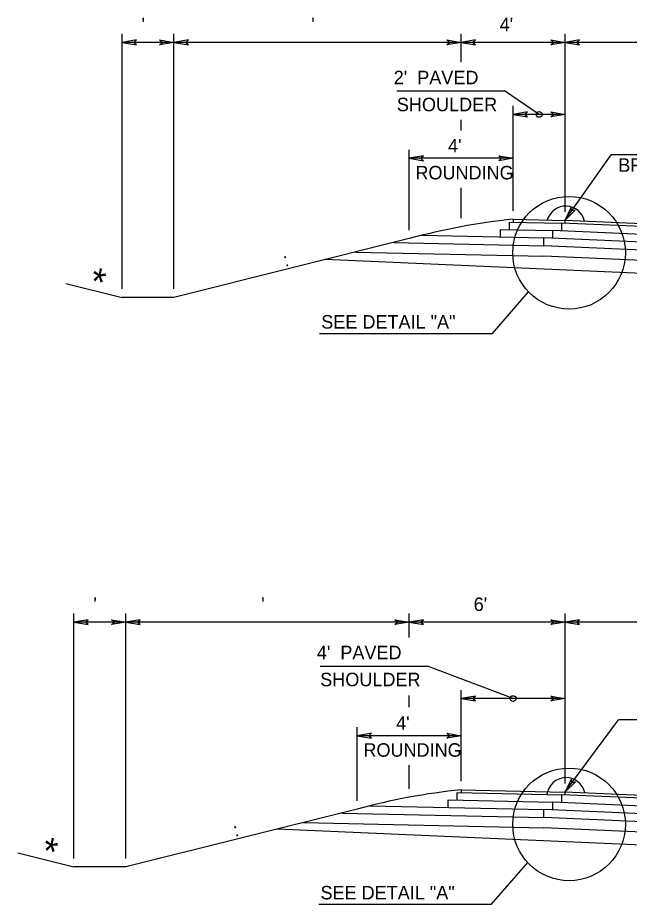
# Model space of a CAD drawing. Extents: x -592 to 1199, y -590 to 416.
# Drawn here: x 726.1 to 789.6, y -200.2 to -108.4 of the extents above; entities that cross this region are included whole.
import ezdxf

# ---------------------------------------------------------------- set-up
doc = ezdxf.new("R2010")
doc.units = 0
doc.layers.add('1', color=7, linetype='Continuous')
doc.layers.add('Des_ Drain_ Ftrs', color=7, linetype='Continuous')

msp = doc.modelspace()

# ---------------------------------------------------------------- linework, layer by layer
at = {"layer": '1'}
for p, q in [((736.954, -136.465), (736.954, -110.022)), ((742.343, -136.465), (742.343, -110.022)), ((772.114, -112.972), (772.114, -110.022)), ((782.89, -128.477), (782.89, -110.022)), ((742.343, -110.902), (736.954, -110.902)), ((772.114, -110.902), (742.343, -110.902)), ((782.89, -110.902), (772.114, -110.902)), ((812.526, -110.902), (782.89, -110.902)), ((765.454, -115.944), (776.595, -115.944)), ((780.196, -118.369), (776.61, -115.923)), ((777.502, -128.359), (777.502, -117.489)), ((782.89, -118.369), (777.502, -118.369)), ((772.114, -120.033), (772.114, -118.951)), ((766.726, -130.369), (766.726, -122.044)), ((777.502, -122.924), (766.726, -122.924)), ((782.884, -129.356), (787.668, -122.553)), ((801.616, -122.553), (787.668, -122.553)), ((772.114, -129.137), (772.114, -125.99)), ((777.124, -129.531), (782.544, -129.641)), ((777.124, -130.312), (777.124, -129.531)), ((777.502, -129.239), (782.884, -129.356)), ((777.502, -129.239), (777.502, -129.539)), ((812.526, -130.651), (782.884, -129.356)), ((782.884, -129.356), (782.884, -129.656)), ((776.199, -130.292), (781.622, -130.41)), ((776.199, -131.081), (776.199, -130.292)), ((812.526, -131.76), (781.622, -130.41)), ((781.622, -131.22), (781.622, -130.41)), ((812.526, -130.951), (782.544, -129.641)), ((782.544, -130.451), (782.544, -129.641)), ((766.726, -131.25), (742.343, -137.345)), ((768.049, -130.903), (780.699, -131.179)), ((812.526, -132.569), (780.699, -131.179)), ((780.699, -131.989), (780.699, -131.179)), ((765.13, -131.649), (780.699, -131.989)), ((812.526, -133.378), (780.699, -131.989)), ((761.163, -132.64), (780.699, -133.067)), ((812.526, -134.457), (780.699, -133.067)), ((812.526, -135.805), (758.025, -133.425)), ((731.127, -135.888), (736.954, -137.345)), ((775.361, -141.079), (779.101, -136.76)), ((742.343, -137.345), (736.954, -137.345)), ((757.429, -141.079), (775.361, -141.079)), ((731.968, -195.499), (731.968, -170.115)), ((737.356, -195.499), (737.356, -170.115)), ((766.726, -172.577), (766.726, -170.115)), ((782.89, -187.728), (782.89, -170.115)), ((737.356, -170.995), (731.968, -170.995)), ((766.726, -170.995), (737.356, -170.995)), ((782.89, -170.995), (766.726, -170.995)), ((812.526, -170.995), (782.89, -170.995)), ((757.505, -175.546), (768.646, -175.546)), ((777.502, -178.922), (768.646, -175.546)), ((772.114, -187.493), (772.114, -178.042)), ((766.726, -179.814), (766.726, -178.597)), ((782.89, -178.922), (772.114, -178.922)), ((761.337, -189.504), (761.337, -181.887)), ((782.884, -188.608), (788.43, -181.138)), ((801.905, -181.138), (788.43, -181.138)), ((772.114, -182.767), (761.337, -182.767)), ((766.726, -188.27), (766.726, -185.833)), ((772.114, -188.373), (782.884, -188.608)), ((772.114, -188.373), (772.114, -188.673)), ((771.698, -188.664), (782.544, -188.893)), ((771.698, -189.445), (771.698, -188.664)), ((812.526, -190.202), (782.544, -188.893)), ((782.544, -189.702), (782.544, -188.893)), ((812.526, -189.902), (782.884, -188.608)), ((782.884, -188.608), (782.884, -188.908)), ((762.662, -190.037), (780.699, -190.431)), ((770.772, -189.425), (781.622, -189.662)), ((770.772, -190.214), (770.772, -189.425)), ((812.526, -191.011), (781.622, -189.662)), ((781.622, -190.471), (781.622, -189.662)), ((761.338, -190.384), (737.356, -196.379)), ((759.741, -190.783), (780.715, -191.241)), ((812.526, -191.82), (780.699, -190.431)), ((780.699, -191.241), (780.699, -190.431)), ((755.775, -191.774), (780.699, -192.318)), ((812.526, -192.63), (780.715, -191.241)), ((812.526, -195.056), (753.038, -192.458)), ((812.526, -193.708), (780.699, -192.318)), ((726.14, -194.922), (731.968, -196.379)), ((737.356, -196.379), (731.968, -196.379)), ((775.278, -200.243), (779.018, -195.923)), ((757.346, -200.243), (775.278, -200.243))]:
    msp.add_line(p, q, dxfattribs=at)
for centre, radius in [((780.196, -118.369), 0.3), ((783.311, -132.715), 5.838), ((777.502, -178.922), 0.3), ((783.311, -191.967), 5.838)]:
    msp.add_circle(centre, radius, dxfattribs=at)
for centre, radius, start, end in [((782.962, -129.87), 1.995, 12.28521, 163.81025), ((784.397, -196.074), 67.19, 95.89012, 105.24869), ((782.991, -189.111), 1.994, 11.96264, 172.11455), ((779.01, -255.206), 67.188, 95.89109, 105.24966)]:
    msp.add_arc(centre, radius, start, end, dxfattribs=at)
at = {"layer": 'Des_ Drain_ Ftrs'}
for points in [[(736.954, -110.902), (738.443, -111.15), (738.148, -110.902), (738.443, -110.654)], [(742.343, -110.902), (740.854, -111.15), (741.149, -110.902), (740.854, -110.654)], [(742.343, -110.902), (743.831, -111.15), (743.536, -110.902), (743.831, -110.654)], [(772.114, -110.902), (770.626, -111.15), (770.921, -110.902), (770.626, -110.654)], [(772.114, -110.902), (773.602, -111.15), (773.307, -110.902), (773.602, -110.654)], [(782.89, -110.902), (781.402, -111.15), (781.697, -110.902), (781.402, -110.654)], [(782.89, -110.902), (784.379, -111.15), (784.084, -110.902), (784.379, -110.654)], [(777.502, -118.369), (778.99, -118.618), (778.695, -118.369), (778.99, -118.121)], [(782.89, -118.369), (781.402, -118.618), (781.697, -118.369), (781.402, -118.121)], [(766.726, -122.924), (768.214, -123.172), (767.919, -122.924), (768.214, -122.676)], [(777.502, -122.924), (776.014, -123.172), (776.309, -122.924), (776.014, -122.676)], [(782.884, -129.356), (783.943, -128.282), (783.571, -128.38), (783.537, -127.996)], [(731.968, -170.995), (733.456, -171.244), (733.161, -170.995), (733.456, -170.747)], [(737.356, -170.995), (735.867, -171.244), (736.162, -170.995), (735.867, -170.747)], [(737.356, -170.995), (738.844, -171.244), (738.549, -170.995), (738.844, -170.747)], [(766.726, -170.995), (765.237, -171.244), (765.532, -170.995), (765.237, -170.747)], [(766.726, -170.995), (768.214, -171.244), (767.919, -170.995), (768.214, -170.747)], [(782.89, -170.995), (781.402, -171.244), (781.697, -170.995), (781.402, -170.747)], [(782.89, -170.995), (784.379, -171.244), (784.084, -170.995), (784.379, -170.747)], [(772.114, -178.922), (773.602, -179.17), (773.307, -178.922), (773.602, -178.673)], [(782.89, -178.922), (781.402, -179.17), (781.697, -178.922), (781.402, -178.673)], [(761.337, -182.767), (762.826, -183.016), (762.531, -182.767), (762.826, -182.519)], [(772.114, -182.767), (770.626, -183.016), (770.921, -182.767), (770.626, -182.519)], [(782.884, -188.608), (783.971, -187.561), (783.596, -187.65), (783.572, -187.265)]]:
    msp.add_lwpolyline(points, close=True, dxfattribs=at)

# ---------------------------------------------------------------- texts
at = {"layer": '1'}
for s, p in [(" '", (738.453, -109.751)), ("  '", (755.532, -109.751)), ("4'", (776.112, -109.751)), ("2'  PAVED", (765.127, -115.244)), ('SHOULDER', (765.452, -118.044)), ("4'", (770.761, -122.308)), ('BREAKOVER', (788.412, -124.32)), ('ROUNDING', (767.373, -125.108)), ('SEE DETAIL "A"', (757.614, -140.576)), (" '", (733.466, -169.844)), ("  '", (750.345, -169.844)), ("6'", (773.418, -169.844)), ("4'  PAVED", (757.154, -174.846)), ('SHOULDER', (757.503, -177.646)), ("4'", (765.373, -182.151)), ('ROUNDING', (761.984, -184.951)), ('SEE DETAIL "A"', (757.531, -199.739))]:
    msp.add_text(s, height=1.4, dxfattribs=at).set_placement(p)
for s, height, rotation, p in [(' : ', 1.4, 14.22821, (753.354, -134.31)), ('*', 2.8, 347.15207, (733.44, -136.913)), (' : ', 1.4, 14.22821, (748.167, -193.394)), ('*', 2.8, 347.15207, (728.453, -195.947))]:
    msp.add_text(s, height=height, rotation=rotation, dxfattribs=at).set_placement(p)

doc.saveas('drawing.dxf')
